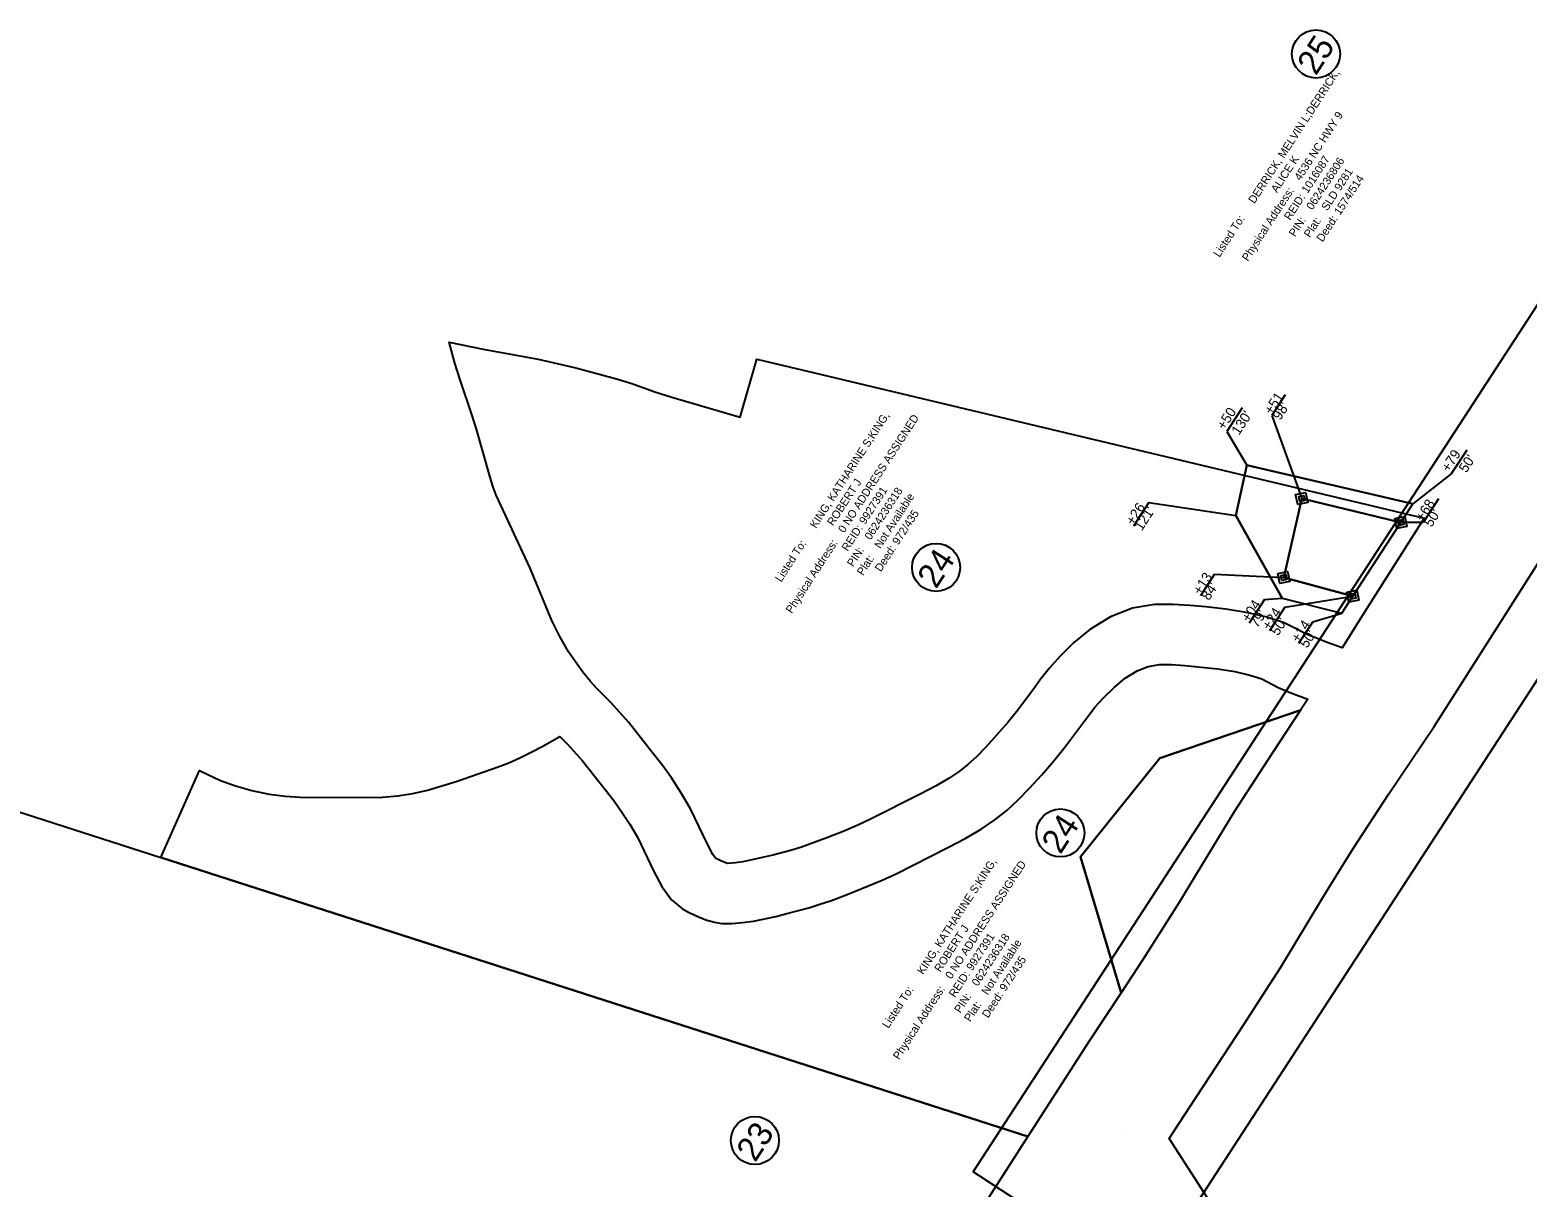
# Model space of a CAD drawing. Extents: x 1019969 to 1024963, y 638146 to 643978.
# Drawn here: x 1022308 to 1023056, y 643201 to 643779 of the extents above; entities that cross this region are included whole.
import ezdxf

# ---------------------------------------------------------------- set-up
doc = ezdxf.new("R2010")
doc.units = 0
for name, color, linetype in [('Old_Level_30', 7, 'Continuous'), ('Pattern 1', 7, 'Continuous'), ('Pattern 2', 7, 'Continuous'), ('Pattern 5', 7, 'Continuous'), ('Prop Easement Permanent Drainage', 7, 'Continuous'), ('Prop Easement Permanent Drainage Station Offsets', 7, 'Continuous'), ('Prop Easement Temporary Drainage', 7, 'Continuous'), ('Prop Easement Temporary Drainage Station Offsets', 7, 'Continuous'), ('Prop Parcel Number CELL', 7, 'Continuous'), ('Prop Parcel Owner Text', 7, 'Continuous'), ('Prop ROW Marker CELL', 7, 'Continuous'), ('Prop ROW Permanent Easement CELL', 7, 'Continuous'), ('Scratch_Level_2', 7, 'Continuous'), ('Scratch_Level_3', 7, 'Continuous'), ('Scratch_Level_4', 7, 'Continuous')]:
    doc.layers.add(name, color=color, linetype=linetype)

msp = doc.modelspace()

# ---------------------------------------------------------------- linework, layer by layer
at = {"layer": 'Old_Level_30'}
msp.add_lwpolyline([(1022266.19, 643400.26), (1022373, 643365.87), (1022806.31, 643226.63), (1022768.38, 643167.56)], dxfattribs=at)
at = {"layer": 'Pattern 1'}
for p, q in [((1022915.75, 643561.84), (1022910.2, 643536.81)), ((1022998.62, 643542.5), (1022915.75, 643561.84)), ((1022915.75, 643561.84), (1022915.75, 643561.84)), ((1022915.75, 643561.84), (1022915.75, 643561.84)), ((1022934.13, 643505.76), (1022943.11, 643545.22)), ((1022943.11, 643545.22), (1022944.53, 643544.88)), ((1022944.53, 643544.88), (1022975.53, 643537.4)), ((1022910.2, 643536.81), (1022929.08, 643503.16)), ((1022975.53, 643537.4), (1022992.62, 643533.29)), ((1022992.62, 643533.29), (1022998.62, 643542.5)), ((1022929.08, 643503.16), (1022933.4, 643495.46)), ((1022934.11, 643505.75), (1022934.13, 643505.76)), ((1022934.12, 643505.73), (1022934.11, 643505.75)), ((1022968.62, 643496.41), (1022934.12, 643505.73)), ((1022933.4, 643495.46), (1022963.16, 643488.03)), ((1022963.16, 643488.03), (1022968.62, 643496.41))]:
    msp.add_line(p, q, dxfattribs=at)
at = {"layer": 'Pattern 2'}
for p, q in [((1022943.11, 643545.22), (1022934.12, 643505.73)), ((1022944.53, 643544.88), (1022943.11, 643545.22)), ((1022975.53, 643537.4), (1022944.53, 643544.88)), ((1022992.62, 643533.29), (1022975.53, 643537.4)), ((1022968.62, 643496.41), (1022992.62, 643533.29)), ((1022934.12, 643505.73), (1022968.62, 643496.41)), ((1022852.89, 643226.91), (1022852.89, 643226.91))]:
    msp.add_line(p, q, dxfattribs=at)
at = {"layer": 'Prop Easement Permanent Drainage'}
for p, q in [((1022934.12, 643505.73), (1022943.11, 643545.22)), ((1022943.11, 643545.22), (1022992.62, 643533.29)), ((1022934.12, 643505.73), (1022968.62, 643496.41))]:
    msp.add_line(p, q, dxfattribs=at)
at = {"layer": 'Prop Easement Permanent Drainage Station Offsets'}
for p, q in [((1022934.85, 643597), (1022928.14, 643586.67)), ((1023011.43, 643545.08), (1023003.76, 643533.28)), ((1022899.48, 643507.35), (1022892.54, 643496.66)), ((1022934.75, 643490.88), (1022927.07, 643479.06))]:
    msp.add_line(p, q, dxfattribs=at)
for points in [[(1022928.14, 643586.67), (1022943.11, 643545.22)], [(1023003.76, 643533.28), (1022992.62, 643533.29)], [(1022899.48, 643507.35), (1022934.12, 643505.73)], [(1022934.75, 643490.88), (1022968.62, 643496.41)]]:
    msp.add_lwpolyline(points, dxfattribs=at)
at = {"layer": 'Prop Easement Temporary Drainage'}
for p, q in [((1022910.2, 643536.81), (1022915.75, 643561.84)), ((1022915.75, 643561.84), (1022998.62, 643542.5)), ((1022933.4, 643495.46), (1022910.2, 643536.81)), ((1022933.4, 643495.46), (1022963.16, 643488.03))]:
    msp.add_line(p, q, dxfattribs=at)
at = {"layer": 'Prop Easement Temporary Drainage Station Offsets'}
for p, q in [((1022913.43, 643590.57), (1022905.65, 643578.62)), ((1023025.55, 643569.44), (1023017.84, 643557.59)), ((1022866.64, 643543.24), (1022858.98, 643531.45)), ((1022924.47, 643494.81), (1022916.79, 643482.99)), ((1022948.61, 643483.67), (1022941.58, 643472.85))]:
    msp.add_line(p, q, dxfattribs=at)
for points in [[(1022905.65, 643578.62), (1022915.75, 643561.84)], [(1023017.84, 643557.59), (1022998.62, 643542.5)], [(1022866.64, 643543.24), (1022910.2, 643536.81)], [(1022924.47, 643494.81), (1022933.4, 643495.46)], [(1022948.61, 643483.67), (1022963.16, 643488.03)]]:
    msp.add_lwpolyline(points, dxfattribs=at)
at = {"layer": 'Prop Parcel Number CELL'}
for p, q in [((1022950.25, 643767.25), (1022950.25, 643767.25)), ((1022760.41, 643510.78), (1022760.41, 643510.78)), ((1022822.5, 643378.17), (1022822.5, 643378.17)), ((1022669.85, 643224.57), (1022669.85, 643224.57))]:
    msp.add_line(p, q, dxfattribs=at)
for centre in [(1022950.25, 643767.25), (1022760.41, 643510.78), (1022822.5, 643378.17), (1022669.85, 643224.57)]:
    msp.add_circle(centre, 12, dxfattribs=at)
at = {"layer": 'Prop ROW Marker CELL'}
for p, q in [((1022943.11, 643545.22), (1022943.11, 643545.22)), ((1022992.62, 643533.29), (1022992.62, 643533.29)), ((1022934.12, 643505.73), (1022934.12, 643505.73)), ((1022968.62, 643496.41), (1022968.62, 643496.41))]:
    msp.add_line(p, q, dxfattribs=at)
at = {"layer": 'Prop ROW Permanent Easement CELL'}
for points in [[(1022940.09, 643547.18), (1022945.07, 643548.24), (1022946.13, 643543.26), (1022941.15, 643542.2)], [(1022941.6, 643546.2), (1022944.09, 643546.73), (1022944.62, 643544.24), (1022942.13, 643543.71)], [(1022989.6, 643535.25), (1022994.58, 643536.3), (1022995.63, 643531.32), (1022990.66, 643530.27)], [(1022991.11, 643534.27), (1022993.6, 643534.79), (1022994.13, 643532.3), (1022991.64, 643531.78)], [(1022931.1, 643507.69), (1022936.08, 643508.75), (1022937.14, 643503.77), (1022932.16, 643502.71)], [(1022932.61, 643506.71), (1022935.1, 643507.24), (1022935.63, 643504.75), (1022933.14, 643504.22)], [(1022965.6, 643498.37), (1022970.58, 643499.43), (1022971.63, 643494.45), (1022966.65, 643493.39)], [(1022967.11, 643497.39), (1022969.6, 643497.92), (1022970.12, 643495.43), (1022967.64, 643494.9)]]:
    msp.add_lwpolyline(points, close=True, dxfattribs=at)
at = {"layer": 'Scratch_Level_2'}
msp.add_lwpolyline([(1022778.99, 643208.83), (1023083.87, 643677.31), (1023355.75, 643500.37), (1023050.87, 643031.89)], close=True, dxfattribs=at)
at = {"layer": 'Scratch_Level_3'}
msp.add_line((1022857.7, 643142.64), (1023194.35, 643659.93), dxfattribs=at)
at = {"layer": 'Scratch_Level_4'}
for points in [[(1022628.31, 643595.88), (1022662.48, 643585.88), (1022670.88, 643614.75), (1022699.61, 643607.92), (1023004.38, 643535.37), (1022974.5, 643488.5), (1022963.31, 643470.64), (1022955.88, 643473.25), (1022944.69, 643477.75), (1022941.31, 643479.69), (1022934.38, 643483.12), (1022925.12, 643486.06), (1022915.37, 643488.25), (1022905.12, 643489.94), (1022895.12, 643491.06), (1022887.12, 643491.81), (1022878.87, 643492.31), (1022869.5, 643492.25), (1022858.62, 643490.44), (1022847.5, 643486.19), (1022837.31, 643479.87), (1022829.13, 643473.06), (1022822.38, 643466.5), (1022816.88, 643460.38), (1022812.81, 643455.19), (1022809.63, 643450.63), (1022801.18, 643439.5), (1022796.31, 643433.38), (1022785.31, 643421.06), (1022780.63, 643416.19), (1022776.3, 643412.31), (1022771.88, 643408.81), (1022766.88, 643405.5), (1022760.37, 643401.69), (1022752.81, 643397.69), (1022727.31, 643384.81), (1022721.31, 643382), (1022714, 643378.87), (1022705.87, 643375.69), (1022693.12, 643371.06), (1022688.31, 643369.56), (1022678.81, 643367), (1022663.9, 643363.74), (1022660.19, 643363.19), (1022656.13, 643362.95), (1022653.13, 643364.06), (1022650.19, 643365.56), (1022648.88, 643367.37), (1022646.13, 643372.62), (1022637.63, 643390.19), (1022632.88, 643398.31), (1022628.11, 643405.69), (1022623.31, 643412.31), (1022618.69, 643418.25), (1022606.63, 643433.44), (1022597.87, 643443.25), (1022591, 643450.13), (1022587.69, 643453.88), (1022583.81, 643458.56), (1022580.12, 643463.63), (1022576.69, 643468.69), (1022572.3, 643476.31), (1022568.37, 643484.25), (1022557.5, 643510.44), (1022553.87, 643518.25), (1022546.31, 643534.44), (1022540.62, 643546.81), (1022539.12, 643550.81), (1022537.37, 643556.38), (1022530.81, 643579.81), (1022528.64, 643586.75), (1022522.5, 643604.5), (1022519.87, 643612.74), (1022517, 643623.38), (1022534, 643619.89), (1022561.62, 643614.75), (1022569.62, 643613.06), (1022580.37, 643610.5), (1022600.62, 643605.06), (1022608.38, 643602.63), (1022619.81, 643598.56)], [(1023375.37, 643414.25), (1023232.66, 643010.18), (1023186.87, 643033.19), (1022911.81, 643171.25), (1022876.86, 643225.56), (1022887.12, 643241.44), (1022914.18, 643282.44), (1022923.5, 643296.94), (1022932.63, 643311.19), (1022953.13, 643345.06), (1022956.89, 643351.1), (1022968.88, 643370.44), (1022986.68, 643397.63), (1023009.31, 643431.38), (1023083.62, 643548.06), (1023092.12, 643560.81), (1023152.81, 643521), (1023271.39, 643501.81), (1023289.88, 643484.25), (1023349.85, 643478.2), (1023369.37, 643476.25), (1023374.6, 643421.76)], [(1022832.63, 643366.31), (1022852.81, 643298.38), (1022836.88, 643274.19), (1022806.31, 643226.63), (1022373, 643365.87), (1022392.37, 643409.31), (1022396.5, 643407.31), (1022402.87, 643404.44), (1022410.31, 643401.63), (1022418.5, 643399.31), (1022427.12, 643397.5), (1022435.12, 643396.5), (1022442.64, 643396), (1022476.88, 643395.88), (1022483.81, 643396), (1022491.19, 643396.63), (1022498.88, 643397.88), (1022506.31, 643399.56), (1022513.38, 643401.63), (1022520.62, 643403.94), (1022541.62, 643411.19), (1022546.81, 643413.25), (1022552.31, 643415.63), (1022558.12, 643418.5), (1022563.62, 643421.31), (1022572.37, 643426.31), (1022576.19, 643422.56), (1022583.62, 643414.19), (1022595, 643399.81), (1022599.31, 643394.31), (1022603.38, 643388.63), (1022607.38, 643382.56), (1022611.13, 643376.06), (1022619.19, 643359.25), (1022623.38, 643351.37), (1022628.19, 643344.81), (1022633.88, 643340.12), (1022637.31, 643338.31), (1022641.31, 643336.5), (1022645.38, 643334.81), (1022649.63, 643333.56), (1022653.38, 643332.94), (1022658.3, 643332.94), (1022663.63, 643333.37), (1022669.13, 643334.19), (1022680.31, 643336.5), (1022685.87, 643337.87), (1022696.87, 643340.81), (1022702.37, 643342.56), (1022708.19, 643344.5), (1022716.81, 643347.69), (1022733.5, 643354.56), (1022740.37, 643357.81), (1022766.63, 643371), (1022775, 643375.44), (1022782.88, 643380.06), (1022789.69, 643384.64), (1022795.81, 643389.44), (1022801.38, 643394.63), (1022807.13, 643400.5), (1022813.31, 643407.25), (1022819.31, 643414.13), (1022824.81, 643421), (1022833.81, 643432.94), (1022836.88, 643437.25), (1022839.81, 643441), (1022844.13, 643445.69), (1022849.31, 643450.75), (1022854.89, 643455.5), (1022860.87, 643459.19), (1022866.37, 643461.31), (1022872.12, 643462.25), (1022878.12, 643462.31), (1022884.69, 643461.88), (1022901.12, 643460.19), (1022909.62, 643458.81), (1022917.19, 643457.06), (1022923.19, 643455.19), (1022931.38, 643450.81), (1022937.69, 643448.13), (1022946.13, 643444.94), (1022942.5, 643439.44), (1022872.19, 643415.5)], [(1022863.87, 643315.19), (1022852.81, 643298.38), (1022832.63, 643366.31), (1022872.19, 643415.5), (1022942.5, 643439.44), (1022928.12, 643417.69), (1022909.37, 643388.69), (1022881.62, 643342.94), (1022872.87, 643329.25)]]:
    msp.add_lwpolyline(points, close=True, dxfattribs=at)

# ---------------------------------------------------------------- texts
at = {"layer": 'Pattern 5'}
for s, rotation, p in [('DERRICK, MELVIN L;DERRICK, ', 56.94406, (1022919.49, 643692.21)), ('4536 NC HWY 9', 56.94406, (1022942.45, 643703.65)), ('ALICE K', 56.94406, (1022930.78, 643697.63)), ('1016087', 56.94406, (1022946.06, 643697.28)), ('0624236806', 56.94406, (1022948.45, 643689.04)), ('SLD 9281', 56.94406, (1022955.93, 643688.62)), ('1574/514', 56.94406, (1022962.27, 643686.44)), ('Physical Address:', 56.94406, (1022916.27, 643663.41)), ('REID:', 56.94406, (1022937.33, 643683.87)), ('Listed To:', 56.94406, (1022902.04, 643665.39)), ('PIN:', 56.94406, (1022939.72, 643675.63)), ('Plat:', 56.94406, (1022947.21, 643675.21)), ('Deed:', 56.94406, (1022953.55, 643673.03)), ('KING, KATHARINE S;KING, ', 56.99063, (1022700.41, 643530)), ('0 NO ADDRESS ASSIGNED', 56.99063, (1022714.45, 643527.74)), ('ROBERT J', 56.99063, (1022708.96, 643531.22)), ('9927391', 56.99063, (1022724.95, 643531.97)), ('0624236318', 56.99063, (1022727.65, 643524.19)), ('Not Available', 56.99063, (1022732.58, 643519.85)), ('972/435', 56.99063, (1022741.54, 643521.71)), ('REID:', 56.99063, (1022716.23, 643518.55)), ('Listed To:', 56.99063, (1022682.98, 643503.16)), ('Physical Address:', 56.99063, (1022688.3, 643487.49)), ('PIN:', 56.99063, (1022718.93, 643510.78)), ('Plat:', 56.99063, (1022723.86, 643506.43)), ('Deed:', 56.99063, (1022732.82, 643508.3)), ('KING, KATHARINE S;KING, ', 56.99063, (1022753.99, 643307.11)), ('0 NO ADDRESS ASSIGNED', 56.99063, (1022768.03, 643304.86)), ('ROBERT J', 56.99063, (1022762.54, 643308.33)), ('9927391', 56.99063, (1022778.53, 643309.08)), ('0624236318', 56.99063, (1022781.23, 643301.3)), ('Not Available', 56.99063, (1022786.16, 643296.96)), ('972/435', 56.99063, (1022795.12, 643298.82)), ('REID:', 56.99063, (1022769.81, 643295.67)), ('Listed To:', 56.99063, (1022736.56, 643280.27)), ('Physical Address:', 56.99063, (1022741.88, 643264.6)), ('PIN:', 56.99063, (1022772.51, 643287.89)), ('Deed:', 56.99063, (1022786.4, 643285.41)), ('Plat:', 56.99063, (1022777.44, 643283.55))]:
    msp.add_text(s, height=4, rotation=rotation, dxfattribs=at).set_placement(p)
at = {"layer": 'Prop Easement Permanent Drainage Station Offsets'}
for s, p in [('+51', (1022928.12, 643586.69)), ("98'", (1022932.35, 643583.93)), ('+68', (1023003.74, 643533.29)), ("50'", (1023007.97, 643530.54)), ('+13', (1022892.52, 643496.68)), ("84'", (1022896.75, 643493.93)), ('+24', (1022927.05, 643479.07)), ("50'", (1022931.29, 643476.32))]:
    msp.add_text(s, height=5, rotation=56.99177, dxfattribs=at).set_placement(p)
at = {"layer": 'Prop Easement Temporary Drainage Station Offsets'}
for s, rotation, p in [('+50', 56.94406, (1022904.47, 643579.1)), ("130'", 56.94406, (1022911.75, 643576.53)), ('+79', 56.94406, (1023016.64, 643558.04)), ("50'", 56.94406, (1023025.37, 643557.71)), ('+26', 56.99177, (1022858.96, 643531.47)), ("121'", 56.99177, (1022863.19, 643528.72)), ('+04', 56.99177, (1022916.77, 643483)), ("79'", 56.99177, (1022921.01, 643480.25)), ('+14', 56.99177, (1022941.56, 643472.87)), ("50'", 56.99177, (1022945.79, 643470.12))]:
    msp.add_text(s, height=5, rotation=rotation, dxfattribs=at).set_placement(p)
at = {"layer": 'Prop Parcel Owner Text'}
for s, rotation, p in [('25', 56.99063, (1022950.23, 643756.07)), ('24', 56.99063, (1022760.44, 643499.67)), ('24', 56.99063, (1022822.53, 643367.07)), ('23', 56.99177, (1022670.03, 643213.28))]:
    msp.add_text(s, height=12.15, rotation=rotation, dxfattribs=at).set_placement(p)

doc.saveas('drawing.dxf')
